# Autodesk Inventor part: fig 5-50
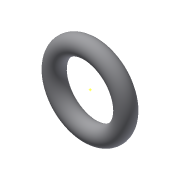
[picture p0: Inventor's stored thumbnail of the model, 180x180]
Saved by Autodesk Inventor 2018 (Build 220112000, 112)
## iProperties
Created: 2010-02
Part Number: fig 5-50
Document SubType Name: Modeling
Designer: CADSoft
Density: 1 g/cm^3
Material: Generic
Appearance: Default
Author: CADSoft
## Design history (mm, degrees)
sketch "Sketch1"
  geometry: L1 (0, 21.37)-(0, -16.247); C1 r 5 at (20.026, 0); 1 further point
  constraints: 2 end point, 1 centre point
  dimensions: "d0" = 10 diameter of C1
revolve "Revolution1" sketch "Sketch1" stored, may be unused: angle "d1" = 90 deg
workpoint "Work Point1"
body "Solid1"
